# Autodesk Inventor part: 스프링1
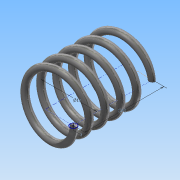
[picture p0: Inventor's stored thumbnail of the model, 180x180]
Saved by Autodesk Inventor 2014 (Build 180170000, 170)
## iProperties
Created: 2016-01
Part Number: 스프링1
Material: 스테인레스 스틸
Document SubType Name: Modeling
Designer: Administrator
Mass: 6.66796 g
Surface Area: 16.7436 cm^2
Volume: 0.825242 cm^3
Density: 8.08 g/cm^3
Appearance: 반연마
Author: Administrator
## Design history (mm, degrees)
sketch "스케치1"
  geometry: L1 (0, 0)-(8.5, 0); L2 (8.5, 0)-(8.5, 20.5); L3 (8.5, 20.5)-(0, 20.5); L4 (0, 20.5)-(0, 0); C1 r 1 at (8.5, 0)
  constraints: 8 end point, 2 parallel, 1 centre point, 1 coincident, 1 horizontal, 1 perpendicular
  dimensions: "d0" = 20.5 distance of L1.end L2.end (derived); "d1" = 2 diameter of C1; "d2" = 17 diameter of L2 L4
feature "코일1" sketch "스케치1" pitch "d3" = 10; turns "d5" = 5; dims "d4" = 20.5 (= d0), "d6" = 0, angle "d7" = 90 deg, angle "d8" = 90 deg, "d9" = 0, "d10" = 0
sketch "스케치2"
  geometry: L1 (-9.5, 0)-(-7.5, 0) reference; 1 further point
  constraints: 1 horizontal alignment
extrude "돌출1" cut sketch "스케치2" distance "d11" = 10; taper "d12" = 0 deg
node "작업 평면1"
sketch "스케치3"
  geometry: L1 (-7.5, 0)-(-9.5, 0) reference; 1 further point
  constraints: 1 horizontal alignment
extrude "돌출2" cut sketch "스케치3" stored distance "d14" = 10; taper "d15" = 0 deg
node "솔리드1"
node "절단 모서리 투영1"
node "절단 모서리 투영2"
other parameters: "d13" = 20.5 (= d0)
